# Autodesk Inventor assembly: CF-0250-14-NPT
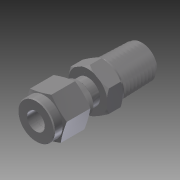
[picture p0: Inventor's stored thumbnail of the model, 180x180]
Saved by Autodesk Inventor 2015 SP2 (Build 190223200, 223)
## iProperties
Created: 2017-11
Part Number: CF-0250-14-NPT
Document SubType Name: Assembly
Designer: JN
Author: JN
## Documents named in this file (5)
- C:\Users\JN\Documents\CAD Drawings\The Sensor Connection\3D\CF\CF-0250-NPT\CF-0250-14-NPT.iam
- C:\Users\JN\Documents\CAD Drawings\The Sensor Connection\3D\CF\CF-0250-NPT\Imported Components\CF-0250-NPT Bottom Ferrule\CF-0250-NPT Bottom Ferrule.ipt
- C:\Users\JN\Documents\CAD Drawings\The Sensor Connection\3D\CF\CF-0250-NPT\Imported Components\CF-0250-NPT Cap\CF-0250-NPT Cap.ipt
- C:\Users\JN\Documents\CAD Drawings\The Sensor Connection\3D\CF\CF-0250-NPT\Imported Components\CF-0250-NPT Top Ferrule\CF-0250-NPT Top Ferrule.ipt
- C:\Users\JN\Documents\CAD Drawings\The Sensor Connection\3D\CF\CF-0250-NPT\Imported Components\CF-0250-14-NPT Threaded Body\CF-0250-14-NPT Threaded Body.ipt
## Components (4 placed, 4 different names)
1. CF-0250-NPT Bottom Ferrule:1 — Mate:5, Mate:6, Mate:7, Mate:10
2. CF-0250-NPT Cap:1 — Mate:5, Mate:8, Mate:9, Rotation:1
3. CF-0250-NPT Top Ferrule:1 — Mate:6, Mate:7, Mate:8
4. CF-0250-14-NPT Threaded Body:1 — Mate:9, Mate:10, Rotation:1
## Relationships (7: Mate 6, RelateRotation 1)
- Mate:5: CF-0250-NPT Bottom Ferrule:1 ↔ CF-0250-NPT Cap:1
- Mate:6: CF-0250-NPT Bottom Ferrule:1 ↔ CF-0250-NPT Top Ferrule:1
- Mate:7: CF-0250-NPT Bottom Ferrule:1 ↔ CF-0250-NPT Top Ferrule:1
- Mate:8: CF-0250-NPT Cap:1 ↔ CF-0250-NPT Top Ferrule:1
- Mate:9: CF-0250-NPT Cap:1 ↔ CF-0250-14-NPT Threaded Body:1
- Mate:10: CF-0250-NPT Bottom Ferrule:1 ↔ CF-0250-14-NPT Threaded Body:1
- Rotation:1 [RelateRotation]: CF-0250-NPT Cap:1 ↔ CF-0250-14-NPT Threaded Body:1
